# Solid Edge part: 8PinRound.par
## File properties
Author: conerly
Template: ansi part.par
Last saved by: alogan
Revision: 24
Application: Solid Edge
Density: 0.03699434701 lbm/in^3
Accuracy: 0.990
Material: ABS Plastic, high impact
Face Style: Red
Fill Style: ANSI34(Plastic)
Virtual Style: Red (Shiny)
Coef. of Thermal Exp: 9e-05
Thermal Conductivity: 0.2
Specific Heat: 0.0
Modulus of Elasticity: 1378951400.0
Poisson's Ratio: 0.4
Yield Stress: 31026406.5
Ultimate Stress: 0.0
Elongation: 0.0
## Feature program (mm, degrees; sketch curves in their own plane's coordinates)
sketch for "unnamed Protrusion 1" plane through (0, 0, 0) normal (0, -1, 0) x-axis (1, 0, 0)
  circle centre (0, 0) radius 12.7
extrude "unnamed Protrusion 1" add finite 25.4 along -normal
sketch for "ExtrudedCutout_1" #1 plane through (0, 0, 0) normal (0, -1, 0) x-axis (1, 0, 0)
  circle centre (0, 10.0399) radius 1.27
sketch for "ExtrudedCutout_1" #2 plane through (0, 0, 0) normal (0, -1, 0) x-axis (1, 0, 0)
  circle centre (0, 4.9599) radius 1.27
extrude "ExtrudedCutout_1" cut finite 3.175 along -normal
pattern "unnamed Pattern 1" of "ExtrudedCutout_1"
extrude "unnamed Cutout 1" cut finite 3.175
extrude "unnamed Cutout 2" cut finite 3.175
extrude "unnamed Cutout 3" cut finite 3.175
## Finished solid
Body 1: solid body, 19 faces, 18 edges, 0 vertices.
  Faces by surface: plane 10, cylinder 9
  Edges by curve: circle 18
Bounding box of the edges (mm): 25.400 x 25.400 x 25.400, from (-12.7, 0, -12.7) to (12.7, 25.4, 12.7).
Cylindrical faces by radius (mm): R1.27 x8, R12.7 x1
Planar faces by outward normal: +y 1, -y 9
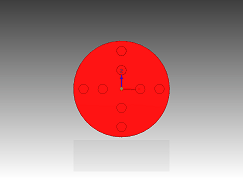
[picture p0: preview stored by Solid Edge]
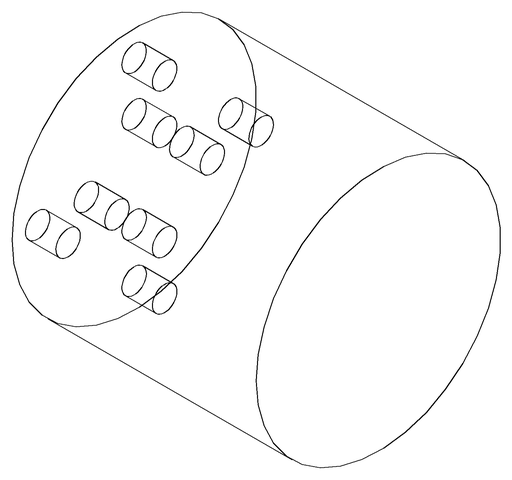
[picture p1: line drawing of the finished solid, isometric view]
